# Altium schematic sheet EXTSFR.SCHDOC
size A4; Organization: Microprocessor-Design Pty Ltd; Address1: 18/110 Caroline Street; Address2: South Yarra; Address3: VIC 3141; Address4: Australia; DocumentNumber: 2; SheetNumber: 2; SheetTotal: 3
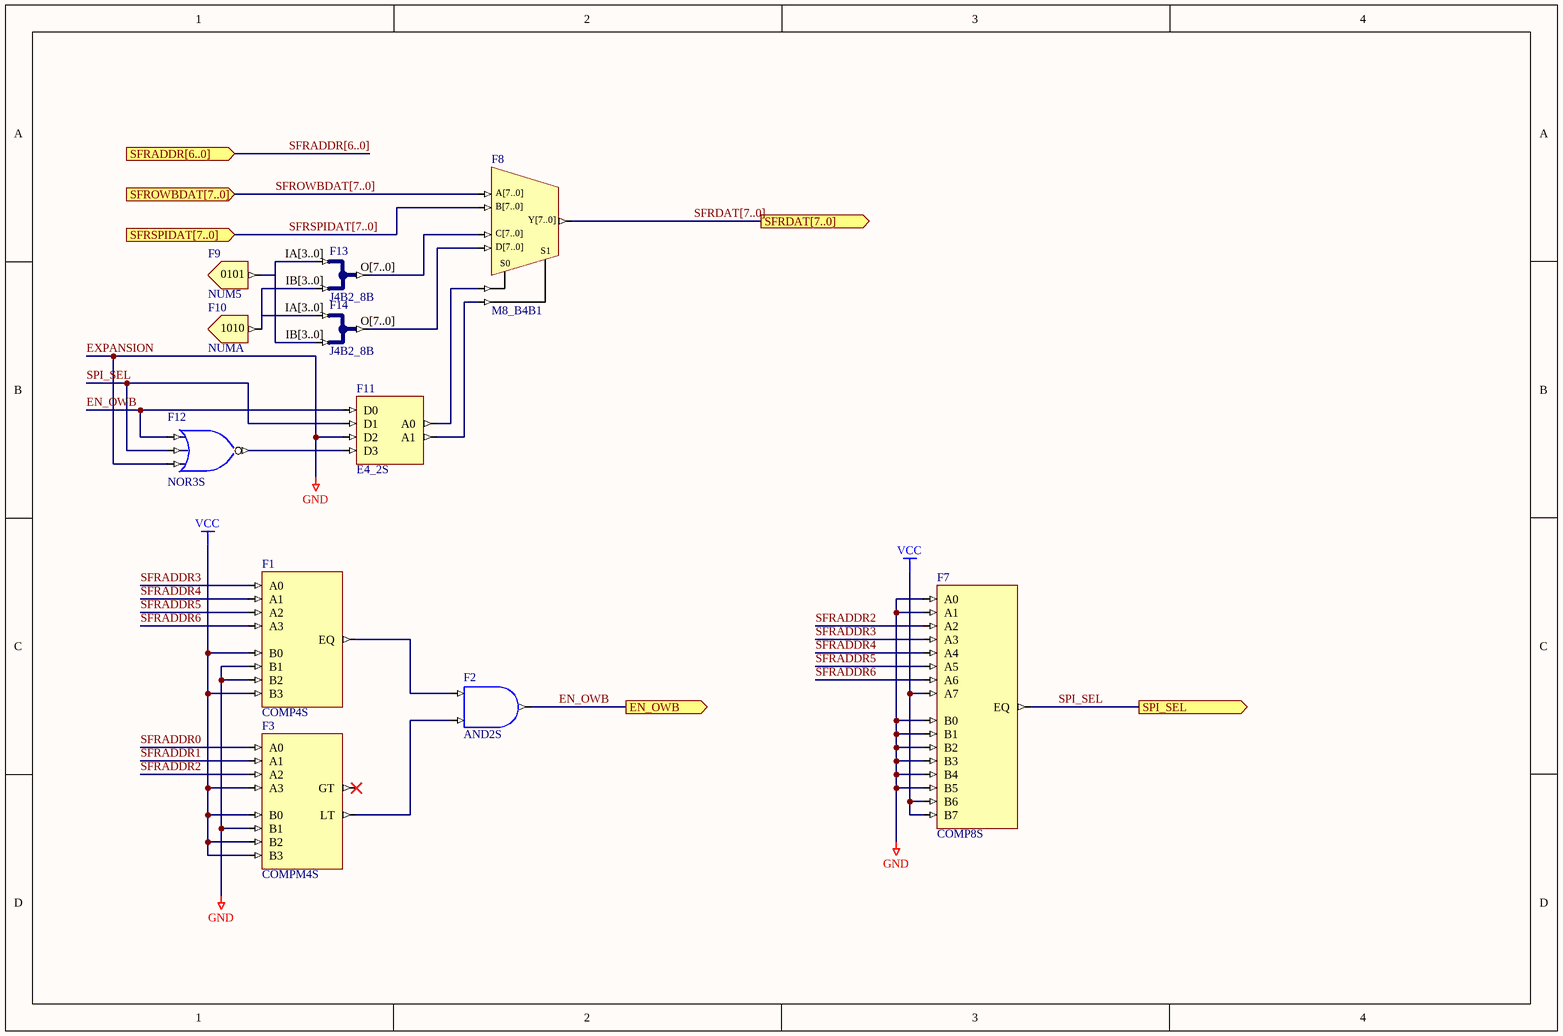
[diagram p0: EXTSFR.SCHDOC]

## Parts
F1  COMP4S
F2  AND2S
F3  COMPM4S
F7  COMP8S
F8  M8_B4B1
F9  NUM5
F10  NUMA
F11  E4_2S
F12  NOR3S
F13  J4B2_8B
F14  J4B2_8B

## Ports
EN_OWB (out), SFRADDR[6..0] (in), SFRDAT[7..0] (out), SFROWBDAT[7..0] (in), SFRSPIDAT[7..0] (in), SPI_SEL (out)

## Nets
EXPANSION: F1.B1 F1.B2 F3.B1 F7.A0 F7.A1 F7.B0 F7.B1 F7.B2 F7.B3 F7.B4 F7.B5 F11.D2 F12.I2  [also labelled GND]
VCC: F1.B0 F1.B3 F3.A3 F3.B0 F3.B2 F3.B3 F7.A7 F7.B6 F7.B7
EN_OWB: F2.O F11.D0 F12.I0 ; port EN_OWB
SFRADDR0: F3.A0
SFRADDR1: F3.A1
SFRADDR2: F3.A2 F7.A2
SFRADDR3: F1.A0 F7.A3
SFRADDR4: F1.A1 F7.A4
SFRADDR5: F1.A2 F7.A5
SFRADDR6: F1.A3 F7.A6
SPI_SEL: F7.EQ F11.D1 F12.I1 ; port SPI_SEL
NetF1_EQ: F1.EQ F2.I0
NetF2_I1: F2.I1 F3.LT
NetF8_S0: F8.S0 F11.A0
NetF8_S1: F8.S1 F11.A1
NetF11_D3: F11.D3 F12.O

Not connected (* = marked no-connect by the designer): F3 GT*; F8 A[7..0] B[7..0] C[7..0] D[7..0] Y[7..0]; F9 O[3..0]; F10 O[3..0]; F13 IA[3..0] IB[3..0] O[7..0]; F14 IA[3..0] IB[3..0] O[7..0]

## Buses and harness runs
bus SFRADDR[6..0] = port SFRADDR[6..0]
bus SFRDAT[7..0] = port SFRDAT[7..0]
bus SFROWBDAT[7..0] = port SFROWBDAT[7..0]
bus SFRSPIDAT[7..0] = port SFRSPIDAT[7..0]

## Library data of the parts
F1 = COMP4S: 4-Bit Identity Comparator, Single Pin Version; Xilinx Equivalent: COMP4; ArchiveName: GENERIC
F2 = AND2S: 2-Input AND Gate, Single Pin Version; Xilinx Equivalent: AND2; ArchiveName: GENERIC
F3 = COMPM4S: 4-Bit Magnitude Comparator, Single Pin Version; Xilinx Equivalent: COMPM4; ArchiveName: GENERIC
F7 = COMP8S: 8-Bit Identity Comparator, Single Pin Version; ArchiveName: GENERIC
F8 = M8_B4B1: 4x8-Bit Bus to 1x8-Bit Bus Multiplexer; ArchiveName: GENERIC
F9 = NUM5: Number Connecter 5; ArchiveName: GENERIC
F10 = NUMA: Number Connecter A; ArchiveName: GENERIC
F11 = E4_2S: 4- to 2-Bit Priority Encoder, Single Pin Version; ArchiveName: GENERIC
F12 = NOR3S: 3-Input NOR Gate, Single Pin Version; Xilinx Equivalent: NOR3; ArchiveName: GENERIC
F13 F14 = J4B2_8B: 2 x 4-Bit input bus to 1 x 8-bit output bus; ArchiveName: GENERIC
